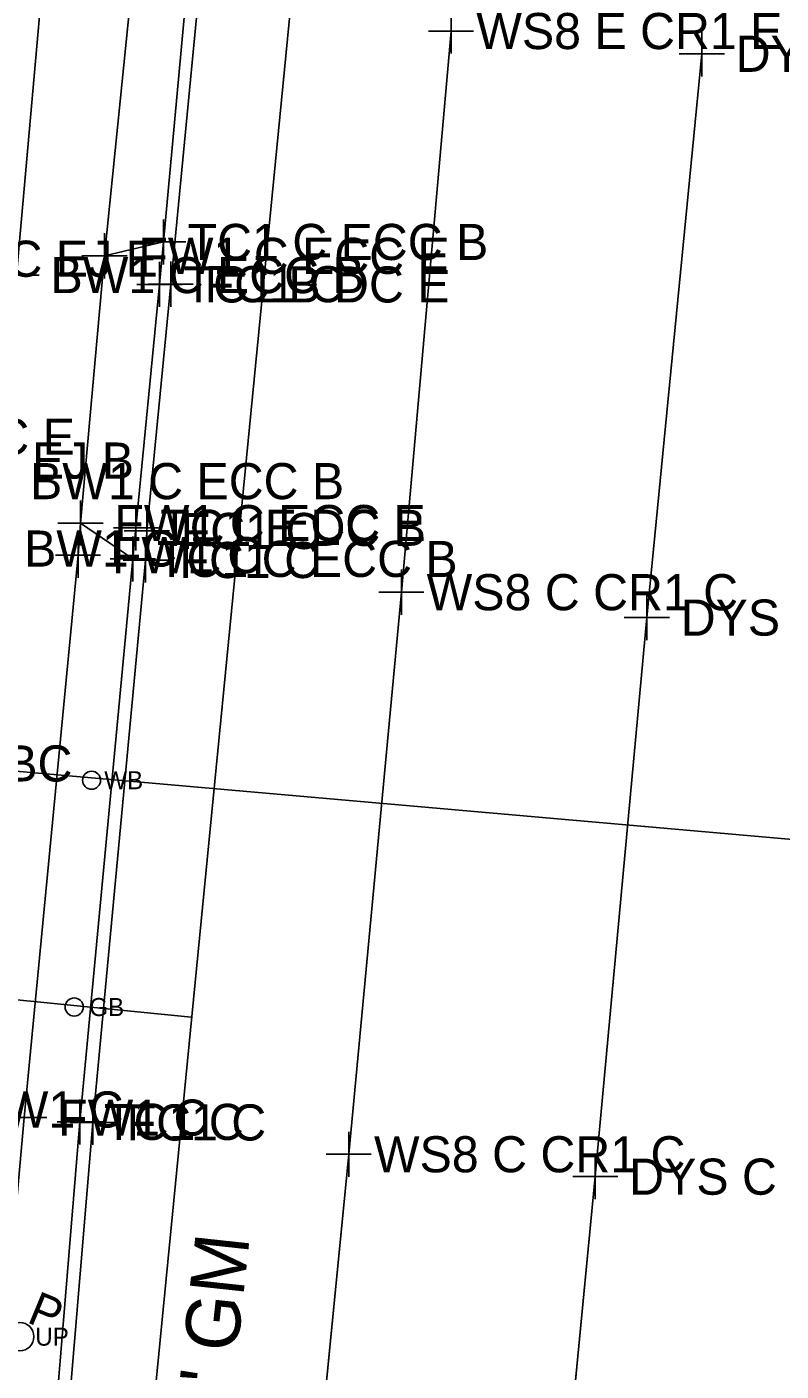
# Model space of a CAD drawing. Extents: x 1363693 to 1365209, y 422201 to 424153.
# Drawn here: x 1364257.9 to 1364291.3, y 423503.7 to 423563.2 of the extents above; entities that cross this region are included whole.
import ezdxf

# ---------------------------------------------------------------- set-up
doc = ezdxf.new("R2010")
doc.units = 0
for name, color, linetype in [('BASELINE-CL-RW', 7, 'Continuous'), ('O-ALGN-BASELINE-WERK-CL-RW', 7, 'Continuous'), ('O-ALGN-TEXT-BASELINE-WERK-CL-RW', 7, 'Continuous'), ('OWNERS', 7, 'Continuous'), ('PM_X_Channelizing_Line', 7, 'Continuous'), ('PM_X_CL_Double_Solid', 7, 'Continuous'), ('SV_X_Original_Ground', 7, 'Continuous'), ('SV_X_Shot_Marker', 7, 'Continuous'), ('UT_X_Gas', 7, 'Continuous'), ('UT_X_Gas_Cells', 7, 'Continuous'), ('UT_X_Gas_Text', 7, 'Continuous'), ('UT_X_Misc_Cells', 7, 'Continuous'), ('UT_X_Unknown_Cells', 7, 'Continuous'), ('UT_X_Water', 7, 'Continuous'), ('UT_X_Water_Text', 7, 'Continuous')]:
    doc.layers.add(name, color=color, linetype=linetype)

msp = doc.modelspace()

# ---------------------------------------------------------------- linework, layer by layer
at = {"layer": 'BASELINE-CL-RW'}
msp.add_line((1364262.745, 423541.033), (1364263.787, 423551.818), dxfattribs=at)
msp.add_line((1364262.745, 423541.033), (1364263.787, 423551.818), dxfattribs=at)
for points in [[(1364263.787, 423551.818), (1364263.96, 423553.7), (1364264.954, 423564.456)], [(1364258.796, 423498.155), (1364259.033, 423499.804), (1364260.262, 423514.707), (1364262.603, 423539.654), (1364262.745, 423541.033)]]:
    msp.add_lwpolyline(points, dxfattribs=at)
at = {"layer": 'O-ALGN-BASELINE-WERK-CL-RW'}
for points in [[(1364238.05, 423150.599), (1364239.504, 423164.947), (1364241.772, 423189.355), (1364244.145, 423214.472), (1364246.386, 423239.049), (1364248.785, 423264.193), (1364251.138, 423289.017), (1364253.53, 423314.189), (1364255.776, 423338.909), (1364258.236, 423363.804), (1364259.261, 423372.435), (1364259.806, 423388.822), (1364262.675, 423414.256), (1364264.7, 423439.017), (1364267.126, 423463.835), (1364268.916, 423478.043), (1364269.753, 423488.631), (1364272.165, 423513.273), (1364274.498, 423538.18), (1364276.696, 423563.046)], [(1364249.902, 423158.791), (1364250.503, 423164.512), (1364252.607, 423188.339), (1364254.923, 423212.972), (1364257.404, 423238.28), (1364259.756, 423263.24), (1364262.23, 423287.907), (1364264.525, 423313.109), (1364266.799, 423338.059), (1364269.18, 423362.6), (1364270.898, 423383.042), (1364271.421, 423387.792), (1364273.694, 423412.788), (1364274.267, 423419.877), (1364276.088, 423437.913), (1364278.182, 423462.848), (1364280.153, 423481.654), (1364280.683, 423487.482), (1364283.085, 423512.281), (1364285.368, 423537.055), (1364287.801, 423562.038)]]:
    msp.add_lwpolyline(points, dxfattribs=at)
at = {"layer": 'O-ALGN-TEXT-BASELINE-WERK-CL-RW'}
for points in [[(1364246.856, 423440.603), (1364248.104, 423453.853), (1364248.377, 423456.684), (1364249.2, 423465.481), (1364251.088, 423485.954), (1364251.263, 423487.647), (1364251.52, 423490.318), (1364252.027, 423495.547), (1364252.167, 423496.873), (1364253.921, 423515.258), (1364256.29, 423540.114), (1364256.554, 423543.102), (1364257.462, 423552.231), (1364258.571, 423564.887)], [(1364250.844, 423440.28), (1364253.104, 423465.04), (1364254.818, 423484.4), (1364255.369, 423489.96), (1364256.279, 423497.969), (1364257.799, 423514.897), (1364260.179, 423539.822), (1364260.288, 423541.243), (1364261.35, 423553.084), (1364262.514, 423564.616)]]:
    msp.add_lwpolyline(points, dxfattribs=at)
at = {"layer": 'OWNERS'}
for p, q in [((1364263.96, 423553.7), (1364261.35, 423553.084)), ((1364262.603, 423539.654), (1364260.288, 423541.243))]:
    msp.add_line(p, q, dxfattribs=at)
msp.add_lwpolyline([(1364253.804, 423440.056), (1364256.188, 423464.718), (1364258.058, 423483.431), (1364258.566, 423489.666), (1364259.443, 423498.094), (1364260.83, 423514.684), (1364263.172, 423539.606), (1364263.224, 423540.892), (1364264.285, 423551.829), (1364265.493, 423564.415)], dxfattribs=at)
at = {"layer": 'PM_X_Channelizing_Line'}
for p, q in [((1364274.498, 423538.18), (1364276.696, 423563.046)), ((1364274.498, 423538.18), (1364276.696, 423563.046)), ((1364285.368, 423537.055), (1364287.801, 423562.038)), ((1364272.165, 423513.273), (1364274.498, 423538.18)), ((1364272.165, 423513.273), (1364274.498, 423538.18)), ((1364283.085, 423512.281), (1364285.368, 423537.055)), ((1364269.753, 423488.631), (1364272.165, 423513.273)), ((1364269.753, 423488.631), (1364272.165, 423513.273)), ((1364280.683, 423487.482), (1364283.085, 423512.281))]:
    msp.add_line(p, q, dxfattribs=at)
at = {"layer": 'PM_X_CL_Double_Solid'}
for p, q in [((1364285.368, 423537.055), (1364287.801, 423562.038)), ((1364283.085, 423512.281), (1364285.368, 423537.055)), ((1364280.683, 423487.482), (1364283.085, 423512.281))]:
    msp.add_line(p, q, dxfattribs=at)
at = {"layer": 'SV_X_Original_Ground'}
for p, q in [((1364276.696, 423562.046), (1364276.696, 423564.046)), ((1364275.696, 423563.046), (1364277.696, 423563.046)), ((1364287.801, 423561.038), (1364287.801, 423563.038)), ((1364286.801, 423562.038), (1364288.801, 423562.038)), ((1364274.498, 423537.18), (1364274.498, 423539.18)), ((1364273.498, 423538.18), (1364275.498, 423538.18)), ((1364285.368, 423536.055), (1364285.368, 423538.055)), ((1364284.368, 423537.055), (1364286.368, 423537.055)), ((1364272.165, 423512.273), (1364272.165, 423514.273)), ((1364271.165, 423513.273), (1364273.165, 423513.273)), ((1364283.085, 423511.281), (1364283.085, 423513.281)), ((1364282.085, 423512.281), (1364284.085, 423512.281))]:
    msp.add_line(p, q, dxfattribs=at)
at = {"layer": 'SV_X_Shot_Marker'}
for p, q in [((1364263.96, 423552.7), (1364263.96, 423554.7)), ((1364261.35, 423552.084), (1364261.35, 423554.084)), ((1364262.96, 423553.7), (1364264.96, 423553.7)), ((1364260.35, 423553.084), (1364262.35, 423553.084)), ((1364263.787, 423550.818), (1364263.787, 423552.818)), ((1364264.285, 423550.829), (1364264.285, 423552.829)), ((1364256.462, 423552.231), (1364258.462, 423552.231)), ((1364262.787, 423551.818), (1364264.787, 423551.818)), ((1364263.285, 423551.829), (1364265.285, 423551.829)), ((1364260.288, 423540.243), (1364260.288, 423542.243)), ((1364262.745, 423540.033), (1364262.745, 423542.033)), ((1364263.224, 423539.892), (1364263.224, 423541.892)), ((1364259.288, 423541.243), (1364261.288, 423541.243)), ((1364260.179, 423538.822), (1364260.179, 423540.822)), ((1364261.745, 423541.033), (1364263.745, 423541.033)), ((1364262.224, 423540.892), (1364264.224, 423540.892)), ((1364262.603, 423538.654), (1364262.603, 423540.654)), ((1364263.172, 423538.606), (1364263.172, 423540.606)), ((1364259.179, 423539.822), (1364261.179, 423539.822)), ((1364261.603, 423539.654), (1364263.603, 423539.654)), ((1364262.172, 423539.606), (1364264.172, 423539.606)), ((1364260.262, 423513.707), (1364260.262, 423515.707)), ((1364260.83, 423513.684), (1364260.83, 423515.684)), ((1364256.799, 423514.897), (1364258.799, 423514.897)), ((1364259.262, 423514.707), (1364261.262, 423514.707)), ((1364259.83, 423514.684), (1364261.83, 423514.684))]:
    msp.add_line(p, q, dxfattribs=at)
at = {"layer": 'UT_X_Gas'}
for p, q in [((1364257.351, 423439.063), (1364269.59, 423564.064)), ((1364265.183, 423519.354), (1364244.357, 423521.42))]:
    msp.add_line(p, q, dxfattribs=at)
at = {"layer": 'UT_X_Gas_Cells'}
msp.add_circle((1364260.009, 423519.798), 0.4, dxfattribs=at)
at = {"layer": 'UT_X_Unknown_Cells'}
msp.add_circle((1364257.597, 423505.192), 0.63, dxfattribs=at)
at = {"layer": 'UT_X_Water'}
msp.add_line((1364245.657, 423531.281), (1364300.863, 423526.417), dxfattribs=at)
msp.add_circle((1364260.78, 423529.849), 0.4, dxfattribs=at)

# ---------------------------------------------------------------- texts
at = {"layer": 'SV_X_Original_Ground'}
for s, p in [('WS8 E CR1 E', (1364277.815, 423562.246)), ('DYS E CR2 E', (1364289.301, 423561.238)), ('WS8 C CR1 C', (1364275.617, 423537.38)), ('DYS C CR2 C', (1364286.868, 423536.255)), ('WS8 C CR1 C', (1364273.284, 423512.473)), ('DYS C CR2 C', (1364284.585, 423511.481))]:
    msp.add_text(s, height=1.6, dxfattribs=at).set_placement(p)
at = {"layer": 'SV_X_Shot_Marker'}
for s, p in [('TC1 C ECC B', (1364265.031, 423552.9)), ('ECC C EJ E', (1364251.944, 423552.157)), ('FW1 C ECC E', (1364262.85, 423552.284)), ('BW1 C ECC B', (1364258.962, 423551.431)), ('TC1 B DC E', (1364264.858, 423551.018)), ('FC1 C', (1364265.785, 423551.029)), ('ECC C ECC3 EC E', (1364241.494, 423544.272)), ('ECC C EJ B', (1364250.887, 423543.214)), ('BW1 C ECC B', (1364258.054, 423542.302)), ('FW1 C ECC E', (1364261.788, 423540.443)), ('TC1 E DC B', (1364263.816, 423540.233)), ('FC1 C', (1364264.724, 423540.092)), ('BW1 C', (1364257.79, 423539.314)), ('FW1 C', (1364261.679, 423539.022)), ('TC1 C ECC B', (1364263.674, 423538.854)), ('FC1 C', (1364264.672, 423538.806)), ('ECC2 EC ECC2 BC', (1364240.788, 423529.791)), ('BW1 C', (1364255.421, 423514.458)), ('FW1 C', (1364259.299, 423514.097)), ('TC1 C', (1364261.333, 423513.907)), ('FC1 C', (1364262.33, 423513.884))]:
    msp.add_text(s, height=1.6, dxfattribs=at).set_placement(p)
at = {"layer": 'UT_X_Gas_Text'}
msp.add_text('GB', height=0.8, dxfattribs=at).set_placement((1364260.677, 423519.398))
msp.add_text('EX. 8" GM', height=2.4, rotation=83.80906, dxfattribs=at).set_placement((1364266.16, 423494.628))
at = {"layer": 'UT_X_Misc_Cells'}
msp.add_text('UP', height=0.8, dxfattribs=at).set_placement((1364258.286, 423504.792))
at = {"layer": 'UT_X_Unknown_Cells'}
msp.add_text('P', height=1.503, rotation=337.58271, dxfattribs=at).set_placement((1364257.866, 423505.843))
at = {"layer": 'UT_X_Water_Text'}
msp.add_text('WB', height=0.8, dxfattribs=at).set_placement((1364261.34, 423529.449))

doc.saveas('drawing.dxf')
